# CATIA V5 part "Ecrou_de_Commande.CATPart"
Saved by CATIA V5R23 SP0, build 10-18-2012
Part number: Ecrou_de_Commande
Material "Bronze": density 8860 kg/m3, Young's modulus 1.1e+11 Pa, Poisson ratio 0.341, thermal expansion 1.78e-05 1/K
Bounding box of the stored display mesh (mm): x -18.952 to 18.952, y -5 to 19.4, z -18.952 to 18.952
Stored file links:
  P:\eleve\Ecrou_de_Commande.CATPart
  d:\catia_soft\intel_a\reffiles\standard\MetricThickPitch.txt
  C:\Program Files\Dassault Systemes\B23\win_b64\startup\materials\French\Catalog.CATMaterial
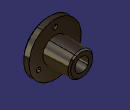
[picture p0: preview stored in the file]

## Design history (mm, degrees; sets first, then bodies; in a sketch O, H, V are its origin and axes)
Body1 (main body)
  Sketch1 "Esquisse.1" on yz-plane, origin (0, 0, 0), H (0, 1, 0), V (0, 0, 1)
    point P1 (-5, 0)
    line L1 (-5, 0) -> (-5, 19)
    line L2 (-5, 19) -> (0, 19)
    point P3 (0, 19)
    line L3 (0, 19) -> (0, 9)
    line L4 (0, 9) -> (19.4, 9)
    line L5 (19.4, 9) -> (19.4, 0)
    point P6 (19.4, 0)
    axis line L6 (-10.0693, 0) -> (26.6, 0)
    point P7 (-10.0693, 0)
    distance L6 L4 = 9
    distance L6 L2 = 19
    distance L3 L1 = 5
    distance L3 L5 = 19.4
    vertical: L1 V, L3 V, L5 V
    coincidence: P3 V, P7 H, P6 L6, P1 L6
    horizontal: L2 H, L4 H, L6 H
  Shaft1: profile Sketch1, axis Sketch1.L6, angle 360
  Chamfer1: length 1, angle 45, on edge [face of Shaft1 | face of Shaft1] (x2)
  Sketch2 "Esquisse.2" on face of Shaft1, origin (0, 19.4, 0), H (1, 0, 0), V (0, 0, -1)
    point P1 (0, 0)
  Hole1: placed by Sketch2, at (0, 19.4, 0) direction (0, -1, 0), diameter 10.106, through (limit type 6), threaded, thread diameter 12, thread depth 24.4, pitch 1.25
  Sketch3 "Esquisse.3" on face of Shaft1, origin (0, -5, 0), H (1, 0, 0), V (0, 0, 1)
    point P1 (0, 14)
    reference intersected line E1 through (0, 0) direction (0, 1) from yz-plane
    reference intersected line E2 through (0, 0) direction (-1, 0) from xy-plane
    distance E2 P1 = 14
    coincidence: P1 E1
  Hole2: placed by Sketch3, at (0, -5, 14) direction (0, 1, 0), diameter 3.5, through (limit type 3), counterbore diameter 6, counterbore depth 3.5
  CircPattern1: of Hole2, instances 3, angular step 120 {= 360.0*1 deg/CircPattern1.AngularNumber}, axis from face of Shaft1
